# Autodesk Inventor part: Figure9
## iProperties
Shininess: 77.0
Length Units: 11269
Angle Units: 11279
Time Units: 11290
Mass Units: 11283
Length Display Precision: 3
Angle Display Precision: 2
Created: 2002-01
Part Number: Figure9
Document SubType Name: Modeling
Designer: ***
Density: 0.0
Volumn: 0.0
Area: 0.0
PropertySet Name: Model Information
Control State: 0
Master: False
Checked Out: False
Author: ***
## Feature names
1. Extrusion1
2. Fillet1
3. Extrusion2
4. Extrusion3
5. Chamfer1
